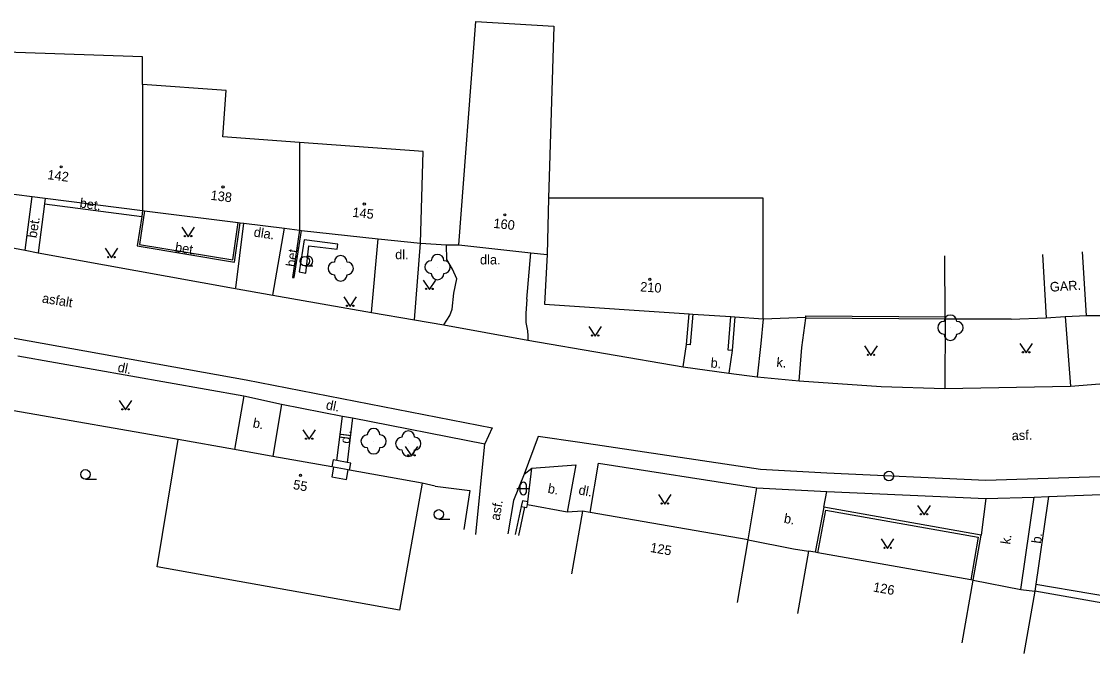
# Model space of a CAD drawing. Extents: x -582162 to -561283, y -1187583 to -1183539.
# Drawn here: x -570907.8 to -570823.6, y -1184956.8 to -1184907 of the extents above; entities that cross this region are included whole.
import ezdxf

# ---------------------------------------------------------------- set-up
doc = ezdxf.new("R2010")
doc.units = 0
for name, color, linetype in [('Vrstva 1', 7, 'Continuous'), ('Vrstva 10', 7, 'Continuous'), ('Vrstva 11', 7, 'Continuous'), ('Vrstva 14', 7, 'Continuous'), ('Vrstva 3', 7, 'Continuous'), ('Vrstva 4', 7, 'Continuous'), ('Vrstva 5', 7, 'Continuous'), ('Vrstva 6', 7, 'Continuous'), ('Vrstva 8', 7, 'Continuous'), ('Vrstva 9', 7, 'Continuous')]:
    doc.layers.add(name, color=color, linetype=linetype)

# ---------------------------------------------------------------- blocks, each defined once
blk = doc.blocks.new('1.079')
at = {"layer": 'Vrstva 1'}
for radius in [0.75, 0.001]:
    blk.add_circle((0, -0.001), radius, dxfattribs=at)
blk = doc.blocks.new('3.130')
at = {"layer": 'Vrstva 1'}
blk.add_circle((0, 0), 0.001, dxfattribs=at)
for centre, start, end in [((0, 1), 0, 180), ((-1, 0), 90, 270), ((1, 0), 270, 90), ((0, -1), 180, 360)]:
    blk.add_arc(centre, 1, start, end, dxfattribs=at)
blk = doc.blocks.new('3.040')
at = {"layer": 'Vrstva 1'}
blk.add_line((0, -0.75), (1.75, -0.75), dxfattribs=at)
blk.add_circle((0, 0), 0.75, dxfattribs=at)
blk = doc.blocks.new('3.110')
at = {"layer": 'Vrstva 1'}
blk.add_line((0, -0.75), (1.25, -0.75), dxfattribs=at)
blk.add_circle((0, 0), 0.75, dxfattribs=at)
blk.add_arc((0.5, 0), 0.75, 249.4944, 109.0474, dxfattribs=at)
blk = doc.blocks.new('3.140')
at = {"layer": 'Vrstva 1'}
blk.add_lwpolyline([(-1, 1.5), (0, 0), (1, 1.5)], dxfattribs=at)
for centre in [(-0.5, 0.1), (0.5, 0.1)]:
    blk.add_circle(centre, 0.1, dxfattribs=at)
blk = doc.blocks.new('3.160')
at = {"layer": 'Vrstva 1'}
for p, q in [((-1, 0), (1, 0)), ((-0.5, -0.5), (-0.5, 0.5)), ((0.5, -0.5), (0.5, 0.5))]:
    blk.add_line(p, q, dxfattribs=at)
for centre, start, end in [((0, 0.5), 0, 180), ((0, -0.5), 180, 360)]:
    blk.add_arc(centre, 0.5, start, end, dxfattribs=at)
blk = doc.blocks.new('4.020')
at = {"layer": 'Vrstva 1'}
blk.add_circle((0, 0), 0.175, dxfattribs=at)

msp = doc.modelspace()

# ---------------------------------------------------------------- linework, layer by layer
at = {"layer": 'Vrstva 10'}
for points in [[(-570907.56, -1184925.03), (-570907.01, -1184920.8)], [(-570905.97, -1184920.94), (-570906.03, -1184921.37)], [(-570906.03, -1184921.37), (-570906.52, -1184925.23)], [(-570906.03, -1184921.37), (-570898.38, -1184922.37)], [(-570890.98, -1184928), (-570890.36, -1184922.91)], [(-570888.08, -1184928.56), (-570887.16, -1184923.31)], [(-570911.48, -1184924.29), (-570907.56, -1184925.03)], [(-570880.3, -1184929.92), (-570879.78, -1184924.13)], [(-570876.92, -1184930.51), (-570876.45, -1184924.49)], [(-570907.56, -1184925.03), (-570906.52, -1184925.23)], [(-570906.52, -1184925.23), (-570891.16, -1184928.02)], [(-570874.39, -1184925.76), (-570874.41, -1184924.6)], [(-570868.09, -1184928.88), (-570867.79, -1184925.23)], [(-570873.95, -1184926.53), (-570874.39, -1184925.76)], [(-570962.98, -1184926.67), (-570955.25, -1184926.66), (-570946.96, -1184927.24), (-570926.98, -1184929.16), (-570911.93, -1184931.33), (-570890.18, -1184935.24), (-570870.81, -1184939.01), (-570871.39, -1184940.27)], [(-570873.6, -1184927.28), (-570873.95, -1184926.53)], [(-570873.83, -1184928.42), (-570873.6, -1184927.28)], [(-570891.16, -1184928.02), (-570888.08, -1184928.56)], [(-570888.08, -1184928.56), (-570880.3, -1184929.92)], [(-570873.96, -1184929.67), (-570873.83, -1184928.42)], [(-570868.09, -1184928.88), (-570868.17, -1184930.02)], [(-570880.3, -1184929.92), (-570876.92, -1184930.51)], [(-570874.63, -1184930.91), (-570874.15, -1184930.17)], [(-570874.15, -1184930.17), (-570873.96, -1184929.67)], [(-570868.17, -1184930.02), (-570868.17, -1184930.71)], [(-570849.5, -1184930.43), (-570849.7, -1184932.36)], [(-570846.47, -1184932.69), (-570846.15, -1184930.39)], [(-570825.77, -1184930.26), (-570825.35, -1184935.72)], [(-570876.92, -1184930.51), (-570874.63, -1184930.91)], [(-570874.63, -1184930.91), (-570868.02, -1184932.12)], [(-570868.17, -1184930.71), (-570868.05, -1184931.38)], [(-570835.19, -1184930.47), (-570835.23, -1184935.9)], [(-570868.05, -1184931.38), (-570868.01, -1184931.78)], [(-570868.01, -1184931.78), (-570868.02, -1184932.12)], [(-570868.02, -1184932.12), (-570855.81, -1184934.2)], [(-570855.81, -1184934.2), (-570855.54, -1184932.46)], [(-570851.95, -1184932.92), (-570852.2, -1184934.71)], [(-570849.7, -1184932.36), (-570849.97, -1184935)], [(-570846.67, -1184935.32), (-570846.47, -1184932.69)], [(-570908.13, -1184933.33), (-570890.36, -1184936.5)], [(-570855.81, -1184934.2), (-570852.2, -1184934.71)], [(-570852.2, -1184934.71), (-570849.97, -1184935)], [(-570849.97, -1184935), (-570846.67, -1184935.32)], [(-570846.67, -1184935.32), (-570840.23, -1184935.76), (-570835.23, -1184935.9)], [(-570825.35, -1184935.72), (-570822.37, -1184935.5)], [(-570835.23, -1184935.9), (-570825.35, -1184935.72)], [(-570890.36, -1184936.5), (-570891.08, -1184940.71)], [(-570890.36, -1184936.5), (-570887.38, -1184937.15)], [(-570887.38, -1184937.15), (-570888.08, -1184941.25)], [(-570887.38, -1184937.15), (-570882.59, -1184938.08)], [(-570883.05, -1184941.58), (-570882.59, -1184938.08)], [(-570882.59, -1184938.08), (-570881.8, -1184938.23)], [(-570881.8, -1184938.23), (-570882.23, -1184941.73)], [(-570881.8, -1184938.23), (-570871.39, -1184940.27)], [(-570812.06, -1184942.43), (-570814.04, -1184942.57), (-570832.01, -1184943.16), (-570844.51, -1184942.58), (-570849.71, -1184942.28), (-570863.92, -1184940.16), (-570867.2, -1184939.69), (-570868.31, -1184942.65)], [(-570872.11, -1184947.39), (-570871.39, -1184940.27)], [(-570883.05, -1184941.58), (-570883.34, -1184941.53), (-570883.44, -1184942.08)], [(-570882.23, -1184941.73), (-570883.05, -1184941.58)], [(-570882.04, -1184942.33), (-570881.94, -1184941.78), (-570882.23, -1184941.73)], [(-570868.31, -1184942.65), (-570867.71, -1184942.18)], [(-570868.01, -1184944.84), (-570867.71, -1184942.18)], [(-570867.71, -1184942.18), (-570864.25, -1184941.93), (-570864.92, -1184945.63)], [(-570863.11, -1184945.67), (-570862.46, -1184941.8), (-570850.02, -1184943.72)], [(-570868.31, -1184942.65), (-570869.14, -1184944.72), (-570869.6, -1184947.36)], [(-570850.68, -1184947.83), (-570850.02, -1184943.72)], [(-570850.02, -1184943.72), (-570844.51, -1184944.02)], [(-570827.08, -1184944.42), (-570814.05, -1184943.92), (-570812.01, -1184943.84)], [(-570844.73, -1184945.25), (-570844.51, -1184944.02)], [(-570844.51, -1184944.02), (-570832, -1184944.56)], [(-570832, -1184944.56), (-570832.36, -1184947.44)], [(-570832, -1184944.56), (-570828.19, -1184944.47)], [(-570829.25, -1184951.73), (-570828.19, -1184944.47)], [(-570828.19, -1184944.47), (-570827.08, -1184944.42)], [(-570827.08, -1184944.42), (-570828.15, -1184951.85)], [(-570828.07, -1184951.3), (-570815.1, -1184953.52)]]:
    msp.add_lwpolyline(points, dxfattribs=at)
at = {"layer": 'Vrstva 11'}
for points in [[(-570885.62, -1184924.22), (-570886.01, -1184926.73)], [(-570882.97, -1184924.55), (-570885.62, -1184924.22)], [(-570883.02, -1184924.94), (-570882.97, -1184924.55)], [(-570885.49, -1184926.83), (-570885.23, -1184924.7)], [(-570885.23, -1184924.7), (-570883.02, -1184924.94)], [(-570886.01, -1184926.73), (-570885.49, -1184926.83)]]:
    msp.add_lwpolyline(points, dxfattribs=at)
at = {"layer": 'Vrstva 4'}
for points in [[(-570910.71, -1184920.34), (-570907.01, -1184920.8), (-570905.97, -1184920.94), (-570898.31, -1184921.91)], [(-570898.31, -1184921.91), (-570898.16, -1184921.93)], [(-570898.16, -1184921.93), (-570890.8, -1184922.85)], [(-570890.8, -1184922.85), (-570890.65, -1184922.87)], [(-570890.65, -1184922.87), (-570890.36, -1184922.91), (-570887.16, -1184923.31)], [(-570887.16, -1184923.31), (-570885.98, -1184923.46)], [(-570885.98, -1184923.46), (-570885.83, -1184923.48)], [(-570885.83, -1184923.48), (-570879.78, -1184924.13), (-570876.45, -1184924.49)], [(-570873.44, -1184924.61), (-570867.79, -1184925.23)], [(-570867.79, -1184925.23), (-570866.51, -1184925.36)], [(-570866.51, -1184925.36), (-570866.71, -1184929.27), (-570855.33, -1184930.04)], [(-570827.55, -1184925.36), (-570827.24, -1184930.35)], [(-570824.09, -1184930.16), (-570824.4, -1184925.17)], [(-570855.33, -1184930.04), (-570855.03, -1184930.06)], [(-570855.03, -1184930.06), (-570852.04, -1184930.26)], [(-570852.04, -1184930.26), (-570851.74, -1184930.28)], [(-570851.74, -1184930.28), (-570849.5, -1184930.43)], [(-570827.24, -1184930.35), (-570825.77, -1184930.26)], [(-570825.77, -1184930.26), (-570824.09, -1184930.16)], [(-570891.08, -1184940.71), (-570895.51, -1184939.92)], [(-570888.08, -1184941.25), (-570891.08, -1184940.71)], [(-570883.44, -1184942.08), (-570888.08, -1184941.25)], [(-570883.29, -1184942.11), (-570883.44, -1184942.08)], [(-570883.29, -1184942.11), (-570883.43, -1184942.87), (-570882.27, -1184943.07), (-570882.14, -1184942.31)], [(-570882.14, -1184942.31), (-570883.29, -1184942.11)], [(-570882.04, -1184942.33), (-570882.14, -1184942.31)], [(-570876.32, -1184943.35), (-570882.04, -1184942.33)], [(-570863.73, -1184945.56), (-570864.59, -1184950.49)], [(-570863.11, -1184945.67), (-570863.73, -1184945.56)], [(-570850.68, -1184947.83), (-570863.11, -1184945.67)], [(-570851.53, -1184952.75), (-570850.68, -1184947.83)], [(-570845.94, -1184948.7), (-570846.82, -1184953.62)], [(-570845.42, -1184948.79), (-570845.94, -1184948.7)], [(-570845.22, -1184948.83), (-570845.42, -1184948.79)], [(-570833.19, -1184950.97), (-570845.22, -1184948.83)], [(-570833.87, -1184955.93), (-570833, -1184951)], [(-570833, -1184951), (-570833.19, -1184950.97)], [(-570828.15, -1184951.85), (-570829.02, -1184956.77)], [(-570815.21, -1184954.14), (-570828.15, -1184951.85)]]:
    msp.add_lwpolyline(points, dxfattribs=at)
at = {"layer": 'Vrstva 5'}
for points in [[(-570873.44, -1184924.61), (-570872.12, -1184907.03)], [(-570872.12, -1184907.03), (-570865.98, -1184907.4)], [(-570865.98, -1184907.4), (-570866.4, -1184920.95)], [(-570898.31, -1184909.81), (-570911.37, -1184909.38)], [(-570898.31, -1184911.99), (-570898.31, -1184909.81)], [(-570891.74, -1184912.47), (-570898.31, -1184911.99)], [(-570898.31, -1184911.99), (-570898.31, -1184921.91)], [(-570892, -1184916.11), (-570891.74, -1184912.47)], [(-570885.98, -1184916.55), (-570892, -1184916.11)], [(-570885.98, -1184916.55), (-570885.98, -1184923.46)], [(-570876.24, -1184917.26), (-570885.98, -1184916.55)], [(-570876.45, -1184924.49), (-570876.24, -1184917.26)], [(-570866.4, -1184920.95), (-570866.51, -1184925.36)], [(-570849.5, -1184920.95), (-570866.4, -1184920.95)], [(-570849.5, -1184922.83), (-570849.5, -1184920.95)], [(-570849.5, -1184930.43), (-570849.5, -1184922.83)], [(-570897.16, -1184949.95), (-570895.51, -1184939.92)], [(-570876.32, -1184943.35), (-570878.11, -1184953.35)], [(-570878.11, -1184953.35), (-570897.16, -1184949.95)]]:
    msp.add_lwpolyline(points, dxfattribs=at)
at = {"layer": 'Vrstva 9'}
for points in [[(-570898.16, -1184921.93), (-570898.57, -1184924.57), (-570891.21, -1184925.79), (-570890.8, -1184922.85)], [(-570898.31, -1184921.91), (-570898.38, -1184922.37)], [(-570898.38, -1184922.37), (-570898.74, -1184924.69), (-570891.08, -1184925.96)], [(-570891.08, -1184925.96), (-570890.65, -1184922.87)], [(-570885.98, -1184923.46), (-570886.53, -1184927.17), (-570886.39, -1184927.19), (-570885.83, -1184923.48)], [(-570876.45, -1184924.49), (-570874.41, -1184924.6)], [(-570874.41, -1184924.6), (-570873.44, -1184924.61)], [(-570835.19, -1184930.27), (-570835.21, -1184925.47)], [(-570855.54, -1184932.46), (-570855.33, -1184930.04)], [(-570855.03, -1184930.06), (-570855.24, -1184932.49), (-570855.54, -1184932.46)], [(-570851.95, -1184932.92), (-570852.25, -1184932.89), (-570852.04, -1184930.26)], [(-570851.74, -1184930.28), (-570851.95, -1184932.92)], [(-570849.5, -1184930.43), (-570846.15, -1184930.29)], [(-570846.15, -1184930.29), (-570846.15, -1184930.19), (-570835.19, -1184930.27)], [(-570846.15, -1184930.39), (-570846.15, -1184930.29)], [(-570835.19, -1184930.47), (-570846.15, -1184930.39)], [(-570835.19, -1184930.47), (-570835.19, -1184930.27)], [(-570830.01, -1184930.45), (-570835.19, -1184930.47)], [(-570830.01, -1184930.45), (-570827.24, -1184930.35)], [(-570824.09, -1184930.16), (-570822.59, -1184930.16)], [(-570895.51, -1184939.92), (-570908.44, -1184937.68)], [(-570875.3, -1184943.61), (-570876.32, -1184943.35)], [(-570875.3, -1184943.61), (-570872.57, -1184943.93), (-570873.04, -1184947.01)], [(-570868.01, -1184944.84), (-570868.45, -1184944.76), (-570868.54, -1184945.2)], [(-570868.54, -1184945.2), (-570869.02, -1184947.41)], [(-570868.73, -1184947.47), (-570868.25, -1184945.25)], [(-570868.54, -1184945.2), (-570868.25, -1184945.25)], [(-570868.25, -1184945.25), (-570868.1, -1184945.28), (-570868.05, -1184945.06)], [(-570868.05, -1184945.06), (-570868.01, -1184944.84)], [(-570864.92, -1184945.63), (-570868.05, -1184945.06)], [(-570863.73, -1184945.56), (-570864.92, -1184945.63)], [(-570844.73, -1184945.25), (-570845.42, -1184948.79)], [(-570845.22, -1184948.83), (-570844.57, -1184945.48), (-570832.6, -1184947.6), (-570833.19, -1184950.97)], [(-570832.36, -1184947.44), (-570844.73, -1184945.25)], [(-570850.68, -1184947.83), (-570847.13, -1184948.52), (-570845.94, -1184948.7)], [(-570833, -1184951), (-570832.36, -1184947.44)], [(-570833, -1184951), (-570829.25, -1184951.73)], [(-570829.25, -1184951.73), (-570828.15, -1184951.85)]]:
    msp.add_lwpolyline(points, dxfattribs=at)

# ---------------------------------------------------------------- block references
at = {"layer": 'Vrstva 1', "xscale": 0.5, "yscale": 0.5}
msp.add_blockref('1.079', (-570839.62, -1184942.8), dxfattribs=at)
at = {"layer": 'Vrstva 11', "xscale": 0.5, "yscale": 0.5}
for p in [(-570875.12, -1184926.36), (-570882.73, -1184926.46), (-570834.78, -1184931.13), (-570880.15, -1184940.06), (-570877.42, -1184940.25)]:
    msp.add_blockref('3.130', p, dxfattribs=at)
at = {"layer": 'Vrstva 3', "xscale": 0.5, "yscale": 0.5}
for name, p in [('3.140', (-570894.74, -1184923.97)), ('3.140', (-570900.77, -1184925.63)), ('3.110', (-570885.56, -1184925.89)), ('3.140', (-570875.76, -1184928.13)), ('3.140', (-570881.99, -1184929.45)), ('3.140', (-570862.73, -1184931.79)), ('3.140', (-570841.03, -1184933.31)), ('3.140', (-570828.83, -1184933.11)), ('3.140', (-570899.66, -1184937.6)), ('3.140', (-570885.21, -1184939.91)), ('3.140', (-570877.17, -1184941.22)), ('3.040', (-570902.81, -1184942.67)), ('3.160', (-570868.37, -1184943.78)), ('3.140', (-570857.25, -1184945.01)), ('3.040', (-570875.02, -1184945.82)), ('3.140', (-570836.86, -1184945.86)), ('3.140', (-570839.72, -1184948.5))]:
    msp.add_blockref(name, p, dxfattribs=at)
at = {"layer": 'Vrstva 8', "xscale": 0.5, "yscale": 0.5}
for p in [(-570904.72, -1184918.47), (-570891.99, -1184920.05), (-570880.88, -1184921.4), (-570869.83, -1184922.25), (-570858.42, -1184927.33), (-570885.9, -1184942.75)]:
    msp.add_blockref('4.020', p, dxfattribs=at)

# ---------------------------------------------------------------- texts
at = {"layer": 'Vrstva 14'}
for s, rotation, p in [('bet.', 351.425, (-570903.3, -1184921.66)), ('bet.', 80.818, (-570906.66, -1184924.11)), ('dla.', 351.458, (-570889.61, -1184923.95)), ('bet.', 351.425, (-570895.8, -1184925.15)), ('bet.', 81.425, (-570886.31, -1184926.38)), ('GAR.', 3.554, (-570826.94, -1184928.3)), ('asfalt', 350.81, (-570906.26, -1184929.15)), ('b.', 354.515, (-570853.67, -1184934.25)), ('k.', 354.515, (-570848.49, -1184934.2)), ('dl.', 348.952, (-570900.32, -1184934.58)), ('dl.', 348.952, (-570883.94, -1184937.54)), ('b.', 348.952, (-570889.69, -1184938.96)), ('dl.', 82.925, (-570882.04, -1184940.28)), ('asf.', 1.887, (-570829.95, -1184939.99)), ('b.', 349.721, (-570866.49, -1184944.12)), ('dl.', 349.721, (-570864.07, -1184944.24)), ('asf.', 80.042, (-570870.25, -1184946.34)), ('b.', 349.56, (-570847.92, -1184946.47)), ('k.', 81.695, (-570830.09, -1184948.21)), ('b.', 81.826, (-570827.67, -1184948.15))]:
    msp.add_text(s, height=0.75, rotation=rotation, dxfattribs=at).set_placement(p)
for s, p in [('dl.', (-570878.45, -1184925.74)), ('dla.', (-570871.78, -1184926.15))]:
    msp.add_text(s, height=0.75, dxfattribs=at).set_placement(p)
at = {"layer": 'Vrstva 6'}
for s, rotation, p in [('142', 352.762, (-570905.83, -1184919.44)), ('138', 352.826, (-570893, -1184921.06)), ('145', 353.815, (-570881.84, -1184922.4)), ('160', 353.859, (-570870.75, -1184923.27)), ('210', 356.132, (-570859.2, -1184928.27)), ('55', 349.876, (-570886.52, -1184943.82)), ('125', 350.154, (-570858.43, -1184948.77)), ('126', 349.911, (-570840.9, -1184951.88))]:
    msp.add_text(s, height=0.75, rotation=rotation, dxfattribs=at).set_placement(p)

doc.saveas('drawing.dxf')
